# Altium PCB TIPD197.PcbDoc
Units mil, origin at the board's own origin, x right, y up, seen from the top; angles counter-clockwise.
Board outline 1210 x 960 mil, 2 copper layers (Top Layer, Bottom Layer), stack 62 mil thick; 31 components, 15 nets, 57 pads, 5 vias.
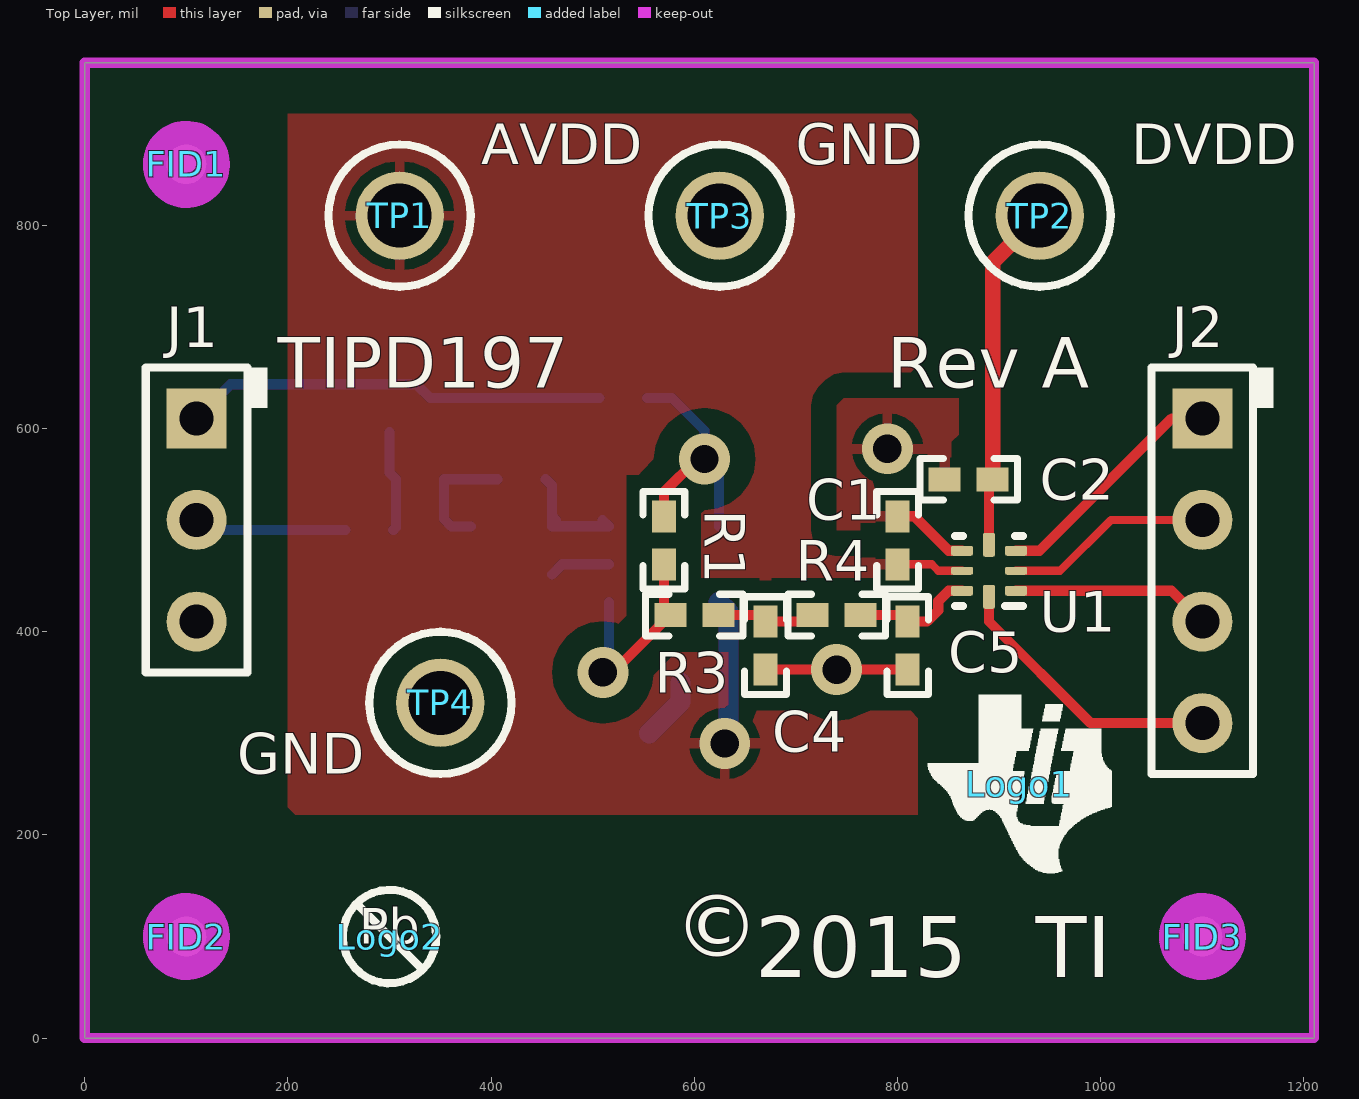
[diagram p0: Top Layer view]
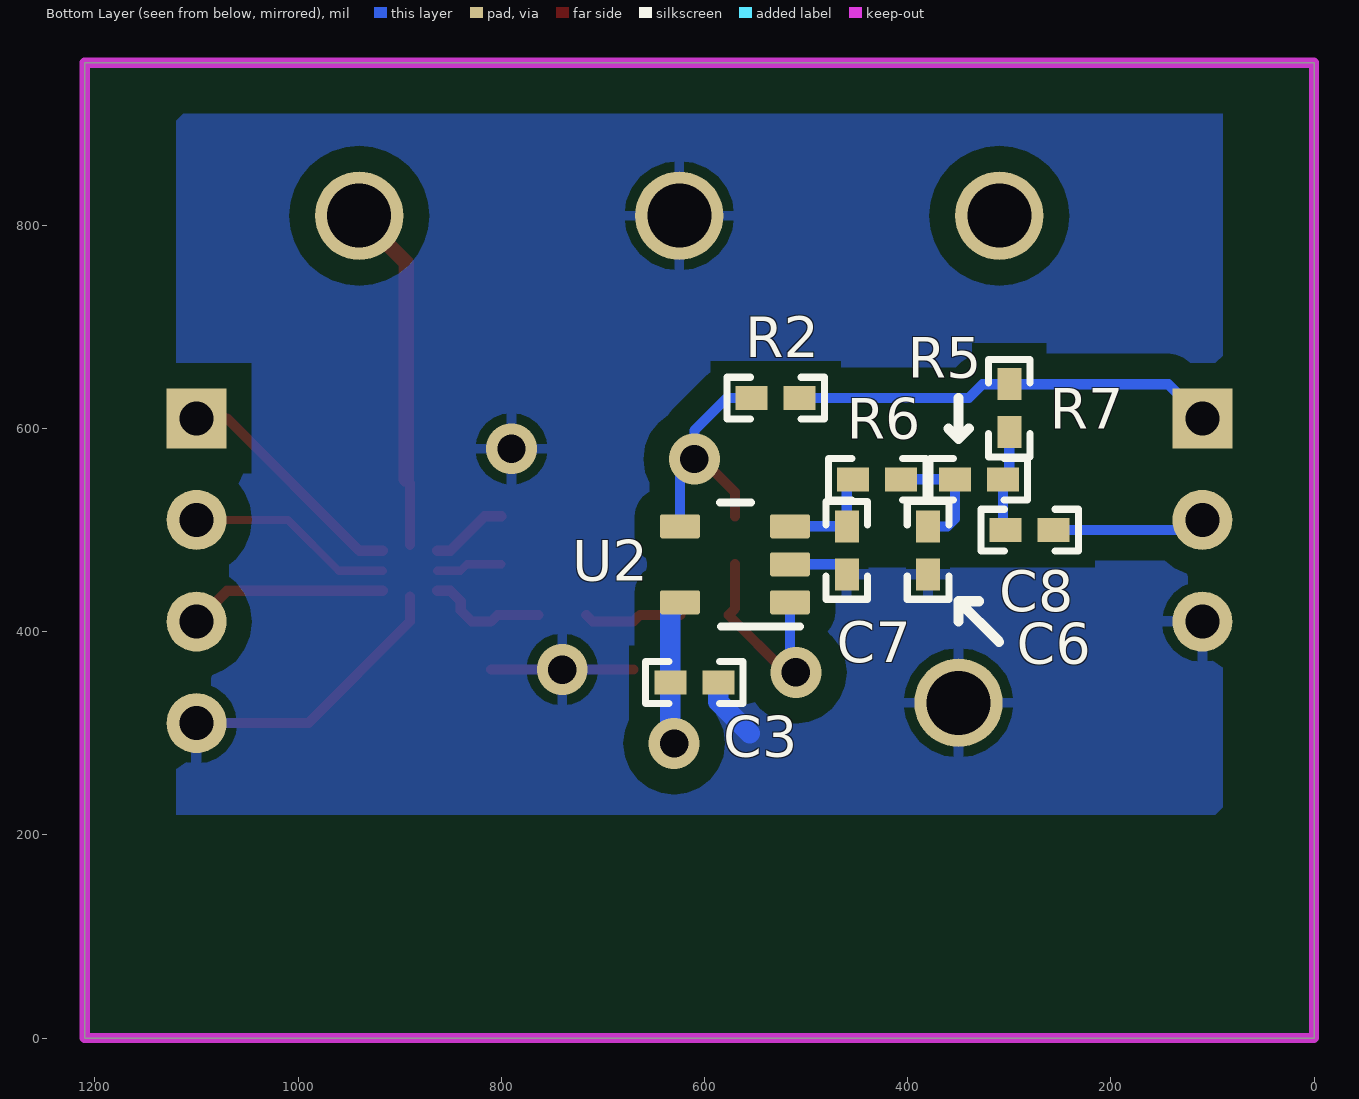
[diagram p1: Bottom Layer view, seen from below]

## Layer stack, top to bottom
Top Solder: solder mask 0.4, Solder Resist, Dk 3.5
Top Layer: signal copper 1.4
Dielectric1: core 59.2, FR-4, Dk 4.8
Bottom Layer: signal copper 1.4
Bottom Solder: solder mask 0.4, Solder Resist, Dk 3.5

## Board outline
0,0 1210,0 1210,960 0,960

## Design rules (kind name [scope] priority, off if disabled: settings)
AcuteAngle [All] p1: minimum=4.50000000000000E+0001 checktracksonly=FALSE
AssemblyTestPointUsage [All] p1: valid=2
Clearance Clearance_Keepouts [((IsTrack Or IsArc) And Not InPoly) And IsFree and IsKeepOut vs ((IsTrack Or IsArc) And Not InPoly) And IsFree and IsKeepOut] p1: gap=0
Clearance Clearance_BoardEdge_MountingHoles [OnCopper and InComponentClass('Mounting Holes') vs IsKeepOut] p2: gap=40
Clearance Clearance_BoardEdge_Poly [OnCopper and InPoly vs IsKeepOut] p3: gap=25
Clearance Clearance_BoardEdge [OnCopper and Not InComponentClass('Logo') and not InComponentClass('FiducialMark') and not InRegion(1000,500,4000,800) and Not IsKeepout vs IsKeepOut] p4: gap=75
Clearance Clearance_Poly [InPolygon] p5: gap=25
Clearance [All] p6: gap=7.87
ComponentClearance ComponentClearance_MountingHoles_FiducialMarks [InComponentClass('Mounting Holes') vs InComponentClass('FiducialMark')] p1: gap=50 collisioncheckmode=3 verticalgap=10 showdistances=FALSE
ComponentClearance ComponentClearance_Shunt [InComponentClass('Header') vs InComponentClass('Shunt')] p2: gap=0 collisioncheckmode=3 verticalgap=0 showdistances=FALSE
ComponentClearance ComponentClearance_Logo [InComponentClass('Logo')] p3: gap=50 collisioncheckmode=3 verticalgap=10 showdistances=FALSE
ComponentClearance ComponentClearance_ScrewToNut [(HasFootprint('NY PMS 440 0025 PH')) vs (HasFootprint('Keystone_1902C'))] p4: gap=5 collisioncheckmode=3 verticalgap=10 showdistances=FALSE
ComponentClearance ComponentClearance_MountingHoles [InComponentClass('Mounting Holes')] p5: gap=250 collisioncheckmode=3 verticalgap=100000 showdistances=FALSE
ComponentClearance ComponentClearance_SmallPassives [HasFootprint('0201*') or HasFootprint('0402*') or HasFootprint('0508') or HasFootprint('0603*') or HasFootprint('0612') or HasFootprint('0805*') or HasFootprint('0815*') or HasFootprint('0830*') or HasFootprint('1206*') or HasFootprint('1210*') or HasFootprint('1808*') or HasFootprint('1812*') or HasFootprint('1825*') or HasFootprint('2010*') or HasFootprint('2220*') or HasFootprint('2225*') or HasFootprint('2512*') or HasFootprint('2728*') or HasFootprint('3518*') vs HasFootprint('0201*') or HasFootprint('0402*') or HasFootprint('0508') or HasFootprint('0603*') or HasFootprint('0612') or HasFootprint('0805*') or HasFootprint('0815*') or HasFootprint('0830*') or HasFootprint('1206*') or HasFootprint('1210*') or HasFootprint('1808*') or HasFootprint('1812*') or HasFootprint('1825*') or HasFootprint('2010*') or HasFootprint('2220*') or HasFootprint('2225*') or HasFootprint('2512*') or HasFootprint('2728*') or HasFootprint('3518*')] p6: gap=20 collisioncheckmode=3 verticalgap=10 showdistances=FALSE
ComponentClearance ComponentClearance_THtoSMT [IsThruComponent vs IsSMTComponent] p7: gap=100 collisioncheckmode=3 verticalgap=30 showdistances=FALSE
ComponentClearance ComponentClearance_THtoTH [IsThruComponent vs IsThruComponent] p8: gap=118.11 collisioncheckmode=3 verticalgap=30 showdistances=FALSE
ComponentClearance [All] p9: gap=40 collisioncheckmode=3 verticalgap=10 showdistances=FALSE
DiffPairsRouting [All] p1: maxlimit=100 minlimit=10 mostfreqgap=10 toplayer_minwidth=15 toplayer_maxwidth=15 toplayer_prefwidth=15 bottomlayer_minwidth=15 bottomlayer_maxwidth=15 bottomlayer_prefwidth=15 maxuncoupledlength=1000
FabricationTestPointUsage TestPointUsage [All] p1: valid=2 allowmultiple=FALSE
FabricationTestpoint Testpoint [All] p1: side=3 testpointundercomponent=TRUE minsize=40 maxsize=100 preferedsize=60 minholesize=0 maxholesize=40 preferedholesize=32 testpointgrid=1 allowsidetop=TRUE allowsidebottom=TRUE usegrid=TRUE gridtolerance=0.01
FanoutControl Fanout_LCC [IsLCC] p1: bgadir=Out bgaviamode=Centered fanoutstyle=Auto fanoutdirection=Alternating viagrid=1 // Fanout_LCC (Default Rule)
FanoutControl Fanout_BGA [IsBGA] p2: bgadir=Out bgaviamode=Centered fanoutstyle=Auto fanoutdirection=Alternating viagrid=1 // Fanout_BGA (Default Rule)
FanoutControl Fanout_Default [All] p4: bgadir=Out bgaviamode=Centered fanoutstyle=Auto fanoutdirection=Alternating viagrid=1 // Fanout_Default (Default Rule)
FanoutControl Fanout_Small [(CompPinCount < 5)] p5: bgadir=Out bgaviamode=Centered fanoutstyle=Auto fanoutdirection=OutThenIn viagrid=1 // Fanout_Small (Default Rule)
HoleSize [All] p1: absolutevalues=TRUE maxlimit=251 minlimit=8 maxpercent=80.000 minpercent=20.000
MinimumAnnularRing MinimumAnnularRing_ThermalPadVias [IsVia and InAnyComponent] p1: minimumring=5.91
MinimumAnnularRing [All] p2: minimumring=9
MinimumSolderMaskSliver MinimumSolderMaskSliver_Logo [InComponentClass('Logo') vs InComponentClass('Logo')] p1: minsoldermaskwidth=0.7
MinimumSolderMaskSliver [All] p2: minsoldermaskwidth=3.94
PlaneConnect [All] p1: planeconnectstyle=Relief reliefexpansion=10 reliefentries=4 reliefconductorwidth=10 reliefairgap=10
PolygonConnect [All] p1: connectstyle=Relief reliefconductorwidth=10 reliefentries=4 polygonreliefangle="90 Angle" airgapwidth=10
RoutingVias ThermalPadVias [IsVia and InAnyComponent] p1: holewidth=7.87 width=19.68 viastyle="Through Hole" minholewidth=7.87 minwidth=19.68 maxholewidth=12.99 maxwidth=23.62
RoutingVias [All] p2: holewidth=16 width=34 viastyle="Through Hole" minholewidth=7.87 minwidth=26 maxholewidth=40 maxwidth=65
SilkToBoardRegionClearance [Not ((IsComment or IsDesignator) And (Hide <> 'False')) and not InRegion(1000,500,4000,800)] p1:
SilkToSilkClearance SilkToSilkClearance_Pb-FreeLogo [(HasFootprint('Pb-Free_Overlay_Medium') OR HasFootprint('Pb-Free_Overlay_Small')) vs (HasFootprint('Pb-Free_Overlay_Medium') OR HasFootprint('Pb-Free_Overlay_Small'))] p1: silktosilkclearance=0
SilkToSilkClearance [All] p2: silktosilkclearance=5
SilkToSolderMaskClearance "Silk to Solder Mask Opening" [All] p1: minsilkscreentomaskgap=1 clearancetoexposedcopper=FALSE
SolderMaskExpansion [All] p1: expansion=1.97
UnpouredPolygon [All] p1: allowunpoured=FALSE
Width [All] p1: maxlimit=100 minlimit=6 preferedwidth=10 checkconnectedcopper=TRUE
14 further rules are at their usual default settings.

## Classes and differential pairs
component class OPA385_ADS7042: C1 C2 C3 C4 C5 C6 C7 C8 J1 J2 R1 R2 R3 R4 R5 R6 R7 TP1 TP2 TP3 TP4 U1 U2
component class Header: J1 J2
component class AssemblyNote: ZZ2 ZZ3 ZZ4
component class FiducialMark: FID1 FID2 FID3
component class TID_Hardware: FID1 FID2 FID3 Logo1 Logo2 ZZ2 ZZ3 ZZ4
component class Logo: Logo1

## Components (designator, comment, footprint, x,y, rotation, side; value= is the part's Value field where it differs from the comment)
C1 "C1005X5R1A105K050BB" 0402 800,490 r270 top
C2 "C1005X5R1A105K050BB" 0402 870,550 r0 top
C3 "C1005X5R1A225K050BC" 0402 610,350 r0 bottom
C4 "GRM155R72A102KA01D" 0402 670,386.38 r270 top
C5 "GRM155R72A102KA01D" 0402 810,386.38 r270 top
C6 "C1005C0G1E102J" 0402 380,480 r270 bottom
C7 "C1005C0G1E102J" 0402 460,480 r270 bottom
C8 "GRM155R61A184KE19D" 0402 280,500 r180 bottom
FID1 "Fiducial" Fiducial10-20 100,860 r0 top
FID2 "Fiducial" Fiducial10-20 100,100 r0 top
FID3 "Fiducial" Fiducial10-20 1100,100 r0 top
J1 "800-10-003-10-001000" Mill-Max_800-10-003-10-001000 110,510 r270 top
J2 "800-10-004-10-001000" Mill-Max_800-10-004-10-001000 1100,460 r270 top
Logo1 "Texas Instruments" TI_Symbol_Overlay_Small 920,250 r0 top
Logo2 "Pb-Free Symbol" Pb-Free_Overlay_Small 300,100 r0 top
R1 "ERJ-2GE0R00X" 0402 570,490 r270 top
R2 "DNP" 0402 530,630 r0 bottom
R3 "CRCW04021K50JNED" 0402 600,416.38 r0 top
R4 "CRCW04021K50JNED" 0402 740,416.38 r0 top
R5 "CRCW04021K50JNED" 0402 330,550 r0 bottom
R6 "CRCW04021K50JNED" 0402 430,550 r0 bottom
R7 "CRCW040210M0FKED" 0402 300,620 r90 bottom
TP1 "AVDD" Keystone5010 309.87,809.5 r180 top
TP2 "DVDD" Keystone5010 939.87,809.5 r180 top
TP3 "GND" Keystone5011 624.87,809.5 r180 top
TP4 "GND" Keystone5011 350,330 r0 top
U1 "ADS7042IRUGR" RUG0008A 890,460 r180 top
U2 "OPA320AIDBVR" DBV0005A_N 570,466.38 r0 bottom
ZZ2 "These assemblies are ESD sensitive, ESD precautions shall be observed." AssemblyNote 225,1439.11 r0 top
ZZ3 "These assemblies must be clean and free from flux and all contaminants. Use of no clean flux is not acceptable." AssemblyNote 225,1350.56 r0 top
ZZ4 "These assemblies must comply with workmanship standards IPC-A-610 Class 2, unless otherwise specified." AssemblyNote 225,1262 r0 top

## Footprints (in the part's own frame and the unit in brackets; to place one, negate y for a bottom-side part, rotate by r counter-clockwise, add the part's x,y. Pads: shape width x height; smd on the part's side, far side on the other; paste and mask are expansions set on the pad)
0402 [mm] "0402 from SM-752 data"
  rect 0.8x0.6 smd: 1(-0.6,0) 2(0.6,0)
  silkscreen extent -1.22,-0.52 1.22,0.52, body extent -0.55,-0.3 0.55,0.3, height 0.6
AssemblyNote [mil] "Assembly Note"
DBV0005A_N [mm] "SOT23, 5-Leads, Body 2.9x1.6mm, Pitch 0.95mm, Lead Span 2.8mm, IPC Medium Density"
  rrect17% 1x0.6 smd: 1(-1.375,0.95) 2(-1.375,0) 3(-1.375,-0.95) 4(1.375,-0.95) 5(1.375,0.95)
  silkscreen extent -1.63,-1.55 0.38,1.55, body extent -1.42,-1.46 1.42,1.46, height 1.09
Fiducial10-20 [mm]
  round 1 smd mask+0.5: 1(0,0)
  Top Layer keep-out circle w1.178: c0,0 r0.5
Keystone5010 [mil] "Keystone Multipurpose loops"
  round 87 hole 63: 1(0,0)
  silkscreen extent -70,-70 70,70, body extent -63,-63 63,62, height 319
Keystone5011 [mil] "Keystone Multipurpose loops"
  round 87 hole 63: 1(0,0)
  silkscreen extent -70,-70 70,70, body extent -63,-63 63,62, height 319
Mill-Max_800-10-003-10-001000 [mm] "Mill-Max"
  rect 1.5x1.5 hole 0.85: 1(-2.54,0)
  round 1.5 hole 0.85: 2(0,0) 3(2.54,0)
  silkscreen extent -3.81,-1.27 3.81,1.78, body extent -3.81,-1.27 3.81,1.27, height 8.13
Mill-Max_800-10-004-10-001000 [mm] "Mill-Max"
  rect 1.5x1.5 hole 0.85: 1(-3.81,0)
  round 1.5 hole 0.85: 2(-1.27,0) 3(1.27,0) 4(3.81,0)
  silkscreen extent -5.08,-1.27 5.08,1.78, body extent -5.08,-1.27 5.08,1.27, height 8.13
Pb-Free_Overlay_Small [mil]
  silkscreen extent -46,-46 46,46
RUG0008A [mm] "QFN, 8-Leads, Body 1.5x1.5mm, Pitch 0.5mm, TI Recommended"
  rrect40% 0.55x0.25 smd: 1(-0.675,0.5) 3(-0.675,-0.5) 5(0.675,-0.5) 7(0.675,0.5)
  rrect50% 0.55x0.2 smd: 2(-0.675,0) 6(0.675,0)
  rrect33% 0.3x0.6 smd: 4(0,-0.65) 8(0,0.65)
  silkscreen extent -0.85,-0.87 0.85,0.87, body extent -0.78,-0.78 0.77,0.77, height 0.41
TI_Symbol_Overlay_Small [mil]
  silkscreen extent -90,-88 91,88

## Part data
C1 C2: "CAP, CERM, 1 µF, 10 V, +/- 10%, X5R, 0402"
C3: "CAP, CERM, 2.2 µF, 10 V, +/- 10%, X5R, 0402"
C4 C5: "CAP, CERM, 1000 pF, 100 V, +/- 10%, X7R, 0402"
C6 C7: "CAP, CERM, 1000 pF, 25 V, +/- 5%, C0G/NP0, 0402"
C8: "CAP, CERM, 0.18 µF, 10 V, +/- 10%, X5R, 0402"
FID1 FID2 FID3: "Fiducial mark.  There is nothing to buy or mount."
J1: "Header, 100mil, 3x1, TH"
J2: "Header, 100mil, 4x1, TH"
Logo1: library part TI_Logo, "Texas Instrument Corporate Signature"
Logo2: library part Pb-Free
R1: "RES, 0, 5%, 0.063 W, 0402"
R2: library part CRCW04020000Z0ED, "RES, 0, 5%, 0.063 W, 0402"
R3 R4 R5 R6: "RES, 1.5 k, 5%, 0.063 W, 0402"
R7: "RES, 10.0 M, 1%, 0.063 W, 0402"
TP1 TP2: library part 5010, "Test Point, Multipurpose, Red, TH"
TP3 TP4: library part 5011, "Test Point, Multipurpose, Black, TH"
U1: "Ultra-Low Power, Ultra-Small Size, 12-Bit, 1-MSPS, SAR ADC, RUG0008A"
U2: "Precision, 20 MHz, 0.9 pA Ib, RRIO, CMOS Operational Amplifier, 1.8 to 5.5 V, -40 to 125 degC, 5-pin SOT23 (DBV0005A), Green (RoHS & no Sb/Br)"
ZZ2 ZZ3 ZZ4: library part AssemblyNote

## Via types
v1: diameter 50, hole 28, Top Layer to Bottom Layer, 5 vias

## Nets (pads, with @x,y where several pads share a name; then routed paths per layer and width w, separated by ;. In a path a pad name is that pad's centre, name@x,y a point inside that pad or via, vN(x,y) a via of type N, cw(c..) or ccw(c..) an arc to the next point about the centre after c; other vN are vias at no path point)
AVDD: C1.2 C3.2 TP1.1 U1.6 U2.5 | length 239.8
  Top Layer w8: C1.2 833.62,466.38 840,460 U1.6
  Bottom Layer w10: TP1.1@309.87,780.13 TP1.1 ; v1(630,290) v1@633.62,293.62
  Bottom Layer w20: U2.5 633.62,419.49 C3.2 v1@633.62,293.62
DVDD: C2.2 TP2.1 U1.4 | length 378.2
  Top Layer w10: U1.4 890,546.38 C2.2 ; TP2.1 TP2.1@963.62,785.74
  Top Layer w15: C2.2 893.62,763.25 TP2.1
GND: C1.1 C2.1 C3.1 C4.2 C5.2 C6.2 C7.2 J1.3 J2.4 TP3.1 TP4.1 U1.5 U1.8 U2.2 | length 616.1
  Top Layer w10: C4.2 C5.2 ; C1.1 816.38,513.62 850.31,479.69 U1.5 ; U1.8 890,410 990,310 J2.4
  Bottom Layer w10: C7.2 470,466.38 U2.2
  Bottom Layer w20: 555.5,300 586.38,330.88 C3.1
  other v1: 740,362.76 790,580
NetC4_1: C4.1 R3.2 R4.1 | length 98
  Top Layer w10: R3.2 663.62,416.38 C4.1 710,410 R4.1
NetC5_1: C5.1 R4.2 U1.7 | length 120.3
  Top Layer w10: R4.2 803.62,416.38 C5.1 829.12,410 840,420.88 840,430 850.32,440.32 U1.7
NetC6_1: C6.1 R5.2 R6.1 | length 121.3
  Bottom Layer w10: C6.1 360.88,503.62 353.62,510.88 R5.2 R6.1
NetC7_1: C7.1 R6.2 U2.3 | length 118.9
  Bottom Layer w10: R6.2 460,543.62 C7.1@460,513.62 ; C7.1@463.62,510 C7.1@460,513.62 ; U2.3@509.65,510 U2.3 460.16,503.78 C7.1 C7.1@460,513.62
NetC8_1: C8.1 R5.1 R7.1 | length 100.2
  Bottom Layer w10: R7.1 300,556.38 R5.1 306.38,502.76 C8.1
NetJ2_1: J2.1 U1.3 | length 237.4
  Top Layer w10: U1.3 939.69,479.69 1070,610 J2.1
NetJ2_2: J2.2 U1.2 | length 204.1
  Top Layer w8: U1.2 960,460 1010,510 J2.2
NetJ2_3: J2.3 U1.1 | length 196
  Top Layer w10: U1.1 1069.68,440.32 J2.3
NetR1_1: R1.1 R2.2 U2.4 | length 246.9
  Top Layer w10: R1.1 570,537.24 602.76,570 v1(610,570)
  Bottom Layer w10: R2.2 578,630 610,598 v1(610,570) 624.13,555.87 U2.4
NetR1_2: R1.2 R3.1 U2.1 | length 213.8
  Top Layer w10: v1(510,360) 520,360 R3.1 570,422.76 R1.2
  Bottom Layer w10: v1(510,360) 515.87,365.87 U2.1
PACEOUT1: C8.2 J1.2 | length 150.5
  Bottom Layer w10: J1.2 120,500 C8.2
VCAP2: J1.1 R2.1 R7.2 | length 415.9
  Bottom Layer w10: J1.1 143.62,643.62 R7.2 326.38,643.62 340,630 R2.1
pads on no net: FID1.1 FID2.1 FID3.1

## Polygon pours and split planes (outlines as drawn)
AVDD on Top Layer "Top Layer-No Net 1" (solid, remove dead copper, pour order 14): 200,910 820,910 820,220 200,220
GND on Top Layer "Top Layer-No Net" (solid, remove dead copper, pour order 10): 740,630 860,630 860,500 740,500
GND on Bottom Layer "Top Layer-No Net 2" (solid, remove dead copper, pour order 16): 90,910 1120,910 1120,220 90,220

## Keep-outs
Keep-Out Layer:
  lines w10: 1210,960 1210,960 ; 1210,960 1210,0 0,0 0,960 1210,960
  text ".Layer_Name" at 577,-858.49 h60

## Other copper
Top Layer:
  text ".Layer_Name" at 577,-858.49 h60
Bottom Layer:
  text ".Layer_Name" at 577,-858.49 h60

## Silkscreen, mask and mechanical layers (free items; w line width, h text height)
Top Overlay:
  text "TIPD197" at 190,640 h50
  text "Rev A" at 790,640 h50
  text "©" at 580,60 h105
  text "2015" at 660,60 h60
  text "TI" at 936,60 h60
  text ".Layer_Name" at 577,-858.49 h60
Bottom Overlay:
  lines w10: 310,390 350,430 ; 330,430 350,430 ; 340,600 350,590 ; 350,410 350,430 ; 350,630 350,590 ; 360,600 350,590
  text ".Layer_Name" at 577,-858.49 h60
Top Paste:
  text ".Layer_Name" at 577,-858.49 h60
Bottom Paste:
  text ".Layer_Name" at 577,-858.49 h60
Top Solder:
  text ".Layer_Name" at 577,-858.49 h60
  text ".Layer_Name" at 577,-858.49 h60
Bottom Solder:
  text ".Layer_Name" at 577,-858.49 h60
Drill Guide:
  text ".Layer_Name" at 577,-858.49 h60
M1 Board Outline:
  lines w10: 0,950 0,0 1210,0 1210,960 0,960
  text ".Layer_Name" at 577,-858.49 h60
M2 Board Dimensions:
  rectangle: 125,-400 500,-275
  rectangle: 0,-275 125,-150
  lines w7: 0,-275 1000,-275 ; 125,-400 125,-150 ; 250,-400 250,-150 ; 500,-400 500,-150 ; 750,-400 750,-150 ; 0,-400 0,-150 1000,-150 1000,-400 0,-400
  text ".Layer_Name" at 577,-858.49 h60
M3 3D STEP Top:
  text ".Layer_Name" at 577,-858.49 h60
M4 3D STEP Bottom:
  text ".Layer_Name" at 577,-858.49 h60
M5 Assembly Top:
  lines w10: -292,-930.17 6308,-930.17 ; -292,-726.83 6310,-726.83 ; -292,-523.5 -292,-1133.5 3713,-1133.5 6310,-1133.5 6310,-523.5 -291.5,-523.5 -291.5,-1133.5 1284,-1133.5 ; 2173,-1133.5 2173,-523.5 ; 3440,-726.83 3440,-523.5 ; 4280,-726.83 4280,-523.5 ; 4902,-1140 4902,-937.17
  text "COMPONENTS MARKED 'DNP' SHOULD NOT BE POPULATED." at 1153.5,-318.5 h60
  text "ASSEMBLY VARIANT:" at 1153,-434 h60
  text ".VariantName" at 2189,-434 h60
  text "PCB VIEWED FROM TOP SIDE" at -228.5,-655.67 h60
  text "BOARD #:" at 2248,-655.67 h60
  text ".PRJ_Number" at 2793.5,-655.67 h60
  text "REV:" at 3638,-655.67 h60
  text ".PCB_Rev" at 3929.5,-655.67 h60
  text "SVN REV:" at 4476,-655.67 h60
  text ".VersionControl_RevNumber" at 4982,-655.67 h60
  text "PLOT NAME =" at -228.5,-1064.34 h60
  text ".plot_File_Name" at 577,-1064.34 h60
  text "GENERATED    :" at 2250,-1064.34 h60
  text ".Print_Date" at 3119.5,-1064.34 h60
  text ".Print_Time" at 3848.5,-1064.34 h60
  text "TEXAS INSTRUMENTS" at 5113,-1064.34 h60
M6 Assembly Bottom:
  lines w10: -292.5,-727.33 6309.5,-727.33 ; -290.5,-930.67 6309.5,-930.67 ; 1115.5,-1140.5 1115.5,-937.67 ; 1737.5,-727.33 1737.5,-524 ; 2577.5,-727.33 2577.5,-524 ; 3844.5,-1134 3844.5,-524 ; 4733.5,-1134 6309,-1134 6309,-524 -292.5,-524 -292.5,-1134 2304.5,-1134 6309.5,-1134 6309.5,-524
  text "COMPONENTS MARKED 'DNP' SHOULD NOT BE POPULATED." at 6102,-318 h60
  text ".VariantName" at 5058,-434 h60
  text "ASSEMBLY VARIANT:" at 6097,-434 h60
  text ".VersionControl_RevNumber" at 1035.5,-656.17 h60
  text "SVN REV:" at 1541.5,-656.17 h60
  text ".PCB_Rev" at 2088,-656.17 h60
  text "REV:" at 2379.5,-656.17 h60
  text ".PRJ_Number" at 3224,-656.17 h60
  text "BOARD #:" at 3769.5,-656.17 h60
  text "PCB VIEWED FROM BOTTOM SIDE" at 6246,-656.17 h60
  text "TEXAS INSTRUMENTS" at 904.5,-1064.84 h60
  text ".Print_Time" at 2169,-1064.84 h60
  text ".Print_Date" at 2898,-1064.84 h60
  text "GENERATED    :" at 3767.5,-1064.84 h60
  text ".plot_File_Name" at 5440.5,-1064.84 h60
  text "PLOT NAME =" at 6246,-1064.84 h60
M9 Title Sheet:
  drawing of 57 lines, arcs and shapes, not listed
  text "1" at 739.84,8036.5 h70
  text "2" at 3235.5,8036.5 h70
  text "3" at 5724.84,8036.5 h70
  text "4" at 8231.51,8036.5 h70
  text "5" at 10730.5,8036.5 h70
  text "6" at 13235.5,8036.5 h70
  text "A" at -416.5,6893.5 h70
  text "A" at 14383.5,6893.5 h70
  text "B" at -416.5,4513.5 h70
  text "B" at 14383.5,4513.5 h70
  text "C" at -416.5,2138.5 h70
  text "C" at 14383.5,2138.5 h70
  text "PROJECT TITLE:" at 11343.5,277.5 h45
  text ".PRJ_Title" at 11393.5,144.17 h70
  text "DESIGNED FOR:" at 11343.5,-23.5 h45
  text ".PRJ_Customer" at 11393.5,-163.5 h70
  text "D" at -416.5,-231.5 h70
  text "D" at 14383.5,-231.5 h70
  text "FILE NAME:" at 11343.5,-323.5 h45
  text ".PCB_File_Name_No_Path" at 11393.5,-443.5 h70
  text "Texas Instruments (TI) and/or its licensors do not warrant the accuracy or completeness of this specification" at 6374,-605.34 h45
  text "ENGINEER:" at 11343.5,-613.5 h45
  text "LAYOUT BY:" at 12848.5,-613.5 h45
  text "or any information contained therein. TI and/or its licensors do not warrant that this design will meet" at 6329.01,-718 h45
  text ".PRJ_Engineer" at 11393.5,-768.49 h70
  text ".PCB_Layout" at 12899,-768.49 h70
  text "the specifications, will be suitable for your application or fit for any particular purpose, or will operate in" at 6329.01,-830.67 h45
  text ".Layer_Name" at 577,-858.49 h60
  text "ALTIUM DESIGNER VERSION:" at 12848.5,-923.5 h45
  text "an implementation. TI and/or its licensors do not warrant that the design is production worthy. You should" at 6329.01,-943.33 h45
  text "completely validate and test your design implementation to confirm the system functionality for your application." at 6374,-1056 h45
  text ".print_Scale" at 11393.5,-1056.83 h70
  text ".Application_BuildNumber" at 12899,-1056.83 h70
  text "1" at 739.84,-1263.5 h70
  text "2" at 3235.5,-1263.5 h70
  text "3" at 5724.84,-1263.5 h70
  text "4" at 8231.51,-1263.5 h70
  text "5" at 10730.5,-1263.5 h70
  text "6" at 13235.5,-1263.5 h70
M10 Fab Notes:
  drawing of 185 lines, arcs and shapes, not listed
  text "DESIGN INFORMATION" at 12381.02,5910 h60
  text "MIN. TRACK WIDTH:" at 11736.46,5730 h60
  text "8" at 12832.7,5730 h60
  text "MIL" at 12987.46,5730 h60
  text "MIN. CLEARANCE:" at 11736.46,5598 h60
  text "0.2" at 12772.7,5598 h60
  text "mm" at 12987.46,5598 h60
  text "MIN. VIA PAD SIZE:" at 11736.46,5466 h60
  text "24" at 12802.71,5466 h60
  text "MIL" at 12987.46,5466 h60
  text "0.05mm (2MIL)" at 12431.46,5324.29 h60
  text "MINIMUM ANNULAR RING" at 11407.23,5320 h60
  text "EXTERNAL" at 13139.46,5320 h60
  text "PER" at 11607.23,5202 h60
  text "IPC-D-275 CLASS 2 LEVEL C" at 11827.23,5202 h60
  text "MIL, HOLES" at 13315.46,5089.71 h60
  text "+/-" at 12923,5089 h60
  text "+/-" at 13777,5089 h60
  text "REGISTRATION TOLERANCES:" at 11407.23,5084 h60
  text "METAL" at 12607,5084 h60
  text "5" at 13183.2,5084 h60
  text "3" at 14016.2,5084 h60
  text "MIL" at 14132.46,5084 h60
  text "MATERIAL:" at 11332.46,4874.54 h60
  text "FR-4 High Tg" at 12318.9,4734.21 h60
  text "FR-408" at 11753.46,4725.64 h60
  text "X" at 12165.46,4725.64 h60
  text "OTHER" at 13241.46,4725.64 h60
  text "62 MIL (1.6mm) +/-10%" at 12073.56,4562.92 h60
  text "THICKNESS:" at 11407.23,4558.64 h60
  text "X" at 11945.4,4558.64 h60
  text "OTHER" at 13358.46,4558.64 h60
  text "TOLERANCE:" at 11407.23,4400.64 h60
  text "X" at 12246.53,4400.64 h60
  text "ANSI IPC-6012 TYPE 3 CLASS 2" at 12433.48,4400.64 h60
  text "OTHER +/-" at 12433.46,4244.64 h60
  text "BOW & TWIST:" at 11407.23,4087.64 h60
  text "X" at 12246.53,4087.64 h60
  text "ANSI IPC-6012 TYPE 3 CLASS 2" at 12433.48,4087.64 h60
  text "OTHER +/-" at 12433.46,3929.13 h60
  text "DRILLING:" at 11332.46,3790.64 h60
  text "REFERENCE:" at 11407.23,3673.64 h60
  text "X" at 12055.46,3673.64 h60
  text "AS SHOWN" at 12242.46,3673.64 h60
  text "X" at 12956.46,3673.64 h60
  text "NC_DRILL FILES" at 13093.46,3673.64 h60
  text "PTH MIN COPPER THICKNESS:" at 11407.23,3515.64 h60
  text "X" at 12757.46,3515.64 h60
  text "1MIL" at 12894.46,3515.64 h60
  text "OTHER" at 13391.46,3515.64 h60
  text "BOARD FINISH:" at 11332.46,3356.64 h60
  text "SILKSCREEN:" at 11487.68,3238.64 h60
  text "X" at 12436.46,3238.64 h60
  text "TOP" at 12562.46,3238.64 h60
  text "X" at 12946.46,3238.64 h60
  text "BOTTOM" at 13073.46,3238.64 h60
  text "SILKSCREEN COLOR:" at 11487.68,3071.64 h60
  text "X" at 12435.42,3071.64 h60
  text "WHITE" at 12562.46,3071.64 h60
  text "OTHER" at 13073.46,3071.64 h60
  text "SOLDER RESIST COLOR:" at 11487.68,2901.64 h60
  text "X" at 12055.42,2742.44 h60
  text "GREEN" at 12182.46,2742.44 h60
  text "BLUE" at 12773.46,2742.44 h60
  text "OTHER" at 13311.46,2742.44 h60
  text "IMMERSION GOLD (ENIG)" at 12393.46,2553.92 h60
  text "ENEPIG" at 13731,2550.64 h60
  text "SURFACE FINISH:" at 11332.46,2549.64 h60
  text "X" at 12206.51,2549.64 h60
  text "IMM. TIN/SILVER OR EQUIV" at 11662,2392.64 h60
  text "OTHER" at 13093.46,2392.64 h60
  text "ARRAY/PANEL:" at 11332.46,2213.64 h60
  text "CUT AND TRIM PER MECH LAYER 1" at 12393.46,2209.35 h60
  text "N.C. ROUTE" at 12393.46,2057.64 h60
  text "X" at 13072.46,2057.64 h60
  text "V. SCORE" at 13259.46,2057.64 h60
  text "CERTIFICATION:" at 11332.46,1920.64 h60
  text "MATERIALS AND WORKMANSHIP FOR ALL PCBS" at 12057.46,1920.64 h60
  text "TO MEET OR EXCEED THE REQUIREMENTS OF:" at 12057.46,1822.64 h60
  text "X" at 11683.96,1686.13 h60
  text "ANSI IPC-A-600F CLASS ->" at 11822.96,1686.13 h60
  text "X" at 13462.02,1686.13 h60
  text "2" at 13580.96,1686.14 h60
  text "1" at 13265.96,1684.64 h60
  text "3" at 13934.96,1684.64 h60
  text "X" at 11686.02,1526.64 h60
  text "UL 94V-0" at 11822.96,1526.64 h60
  text "X" at 12498.02,1526.64 h60
  text "RoHS" at 12634.96,1526.64 h60
  text "OTHER" at 13279.36,1526.64 h60
  text "PER ORDER" at 13676.42,1526.64 h60
  text "ADDITIONAL REQUIREMENTS:" at 11332.46,1385.64 h60
  text "MICROSECTION:" at 11407.23,1270.64 h60
  text "YES" at 12312.96,1270.64 h60
  text "REQUIRED" at 13174.46,1114.49 h60
  text "BARE BOARD ELEC. TEST:" at 11407.23,1111.64 h60
  text "NONE" at 12712.96,1111.64 h60
  text "X" at 13047.46,1111.64 h60
  text "PER ORDER" at 13766.46,1111.64 h60
  text "MANUFACTURER'S UL:" at 11407.23,954.64 h60
  text "RAIL" at 12572.96,950.35 h60
  text "METAL" at 13064.77,950.35 h60
  text "X" at 13440,950 h60
  text "SILK" at 13576.46,950.35 h60
  text ".Layer_Name" at 577,-858.49 h60
M11 Gerber Information:
  lines w10: -292,-930.17 6308,-930.17 ; -292,-726.83 6310,-726.83 ; -292,-523.5 -292,-1133.5 3713,-1133.5 6310,-1133.5 6310,-523.5 -291.5,-523.5 -291.5,-1133.5 1284,-1133.5 ; 2173,-1133.5 2173,-523.5 ; 3440,-726.83 3440,-523.5 ; 4280,-726.83 4280,-523.5 ; 4902,-1140 4902,-937.17
  text "ALL ARTWORK VIEWED FROM TOP SIDE" at -228.5,-655.67 h60
  text "BOARD #:" at 2248,-655.67 h60
  text ".PRJ_Number" at 2793.5,-655.67 h60
  text "REV:" at 3638,-655.67 h60
  text ".PCB_Rev" at 3929.5,-655.67 h60
  text "SVN REV:" at 4476,-655.67 h60
  text ".VersionControl_RevNumber" at 4982,-655.67 h60
  text "LAYER NAME =" at -228.5,-858.49 h60
  text "PLOT NAME =" at -228.5,-1064.34 h60
  text ".plot_File_Name" at 577,-1064.34 h60
  text "GENERATED    :" at 2250,-1064.34 h60
  text ".Print_Date" at 3119.5,-1064.34 h60
  text ".Print_Time" at 3848.5,-1064.34 h60
  text "TEXAS INSTRUMENTS" at 5113,-1064.34 h60
M12 Stackup:
  drawing of 191 lines, arcs and shapes, not listed
  text "Layer" at 9790.58,7830 h60
  text "Name" at 10200.49,7830 h60
  text "Material" at 11130.23,7830 h60
  text "Thickness" at 11990,7830 h60
  text "Constant" at 12639.84,7830 h60
  text "Board Layer Stack" at 13209.7,7830 h60
  text "1" at 9790.58,7710 h60
  text "Top Overlay" at 10200.49,7710 h60
  text "2" at 9790.58,7590 h60
  text "Top Solder" at 10200.49,7590 h60
  text "Solder Resist" at 11130.23,7590 h60
  text "0.40mil" at 11990,7590 h60
  text "3.5" at 12639.84,7590 h60
  text "3" at 9790.58,7470 h60
  text "Top Layer" at 10200.49,7470 h60
  text "Copper" at 11130.23,7470 h60
  text "1.40mil" at 11990,7470 h60
  text "4" at 9790.58,7350 h60
  text "Dielectric1" at 10200.49,7350 h60
  text "FR-4" at 11130.23,7350 h60
  text "59.20mil" at 11990,7350 h60
  text "4.8" at 12639.84,7350 h60
  text "5" at 9790.58,7230 h60
  text "Bottom Layer" at 10200.49,7230 h60
  text "Copper" at 11130.23,7230 h60
  text "1.40mil" at 11990,7230 h60
  text "6" at 9790.58,7110 h60
  text "Bottom Solder" at 10200.49,7110 h60
  text "Solder Resist" at 11130.23,7110 h60
  text "0.40mil" at 11990,7110 h60
  text "3.5" at 12639.84,7110 h60
  text "7" at 9790.58,6990 h60
  text "Bottom Overlay" at 10200.49,6990 h60
  text ".Layer_Name" at 577,-858.49 h60
M13 Component Bodies Top:
  text ".Layer_Name" at 577,-858.49 h60
M14 Component Bodies Bottom:
  text ".Layer_Name" at 577,-858.49 h60
M15 Courtyards Top:
  text ".Layer_Name" at 577,-858.49 h60
M16 Courtyards Bottom:
  text ".Layer_Name" at 577,-858.49 h60
Drill Drawing:
  circle w3.33: c5572.72,3071.72 r24.89
  lines w3.33: 5547.83,2947.29 5597.6,2947.29 5572.72,2897.52 5547.83,2947.29 ; 5547.83,3208.6 5560.27,3208.6 5572.72,3196.16 5585.16,3208.6 5597.6,3208.6 5585.16,3221.04 5597.6,3233.49 5585.16,3233.49 5572.72,3245.93 5560.27,3233.49 5547.83,3233.49 5560.27,3221.04 5547.83,3208.6
  lines w12: 5480,2852.72 7598.02,2852.72 ; 5480,3300.68 7598.02,3300.68 ; 5850.36,2703.4 5850.36,3450 ; 6207.36,2703.4 6207.36,3450 ; 6868.93,2703.4 6868.93,3450 ; 7153.07,2703.4 7153.07,3450 ; 5480,2703.4 7598.02,2703.4 7598.02,3450 5480,3450 5480,2703.4
  text "Symbol" at 5569.59,3345.48 h72
  text "Quantity" at 5895.16,3345.48 h72
  text "Finished Hole Size" at 6252.16,3345.48 h72
  text "Plated" at 6913.72,3345.48 h72
  text "Hole Type" at 7197.86,3345.48 h72
  text "5" at 5895.16,3196.16 h60
  text "28.00mil (0.711mm)" at 6252.16,3196.16 h60
  text "PTH" at 6913.72,3196.16 h60
  text "Round" at 7197.86,3196.16 h60
  text "7" at 5895.16,3046.84 h60
  text "33.46mil (0.850mm)" at 6252.16,3046.84 h60
  text "PTH" at 6913.72,3046.84 h60
  text "Round" at 7197.86,3046.84 h60
  text "4" at 5895.16,2897.52 h60
  text "63.00mil (1.600mm)" at 6252.16,2897.52 h60
  text "PTH" at 6913.72,2897.52 h60
  text "Round" at 7197.86,2897.52 h60
  text "16 Total" at 5895.16,2748.2 h60
  text ".Layer_Name" at 577,-858.49 h60

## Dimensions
0,0 to 1210,0 on M2 Board Dimensions
0,0 to 0,960 on M2 Board Dimensions
0,-400 to 1000,-400 on M2 Board Dimensions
